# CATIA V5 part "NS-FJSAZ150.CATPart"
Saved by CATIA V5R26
Part number: NS-FJSAZ150
Bounding box of the stored display mesh (mm): x -60 to 120, y 0 to 198, z -60 to 60
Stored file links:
  R:\Document\坂尻\その他\ナベヤデータ変換\安全カバーキャスター\MCBJSAZ150\NS-FJSAZ150.CATPart
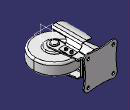
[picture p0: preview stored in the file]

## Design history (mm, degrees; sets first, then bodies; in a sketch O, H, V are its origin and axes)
Body1 (main body)
  Solid1: solid without history
  Body2
    Solid2: solid without history
  Assemble1: tool Body2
